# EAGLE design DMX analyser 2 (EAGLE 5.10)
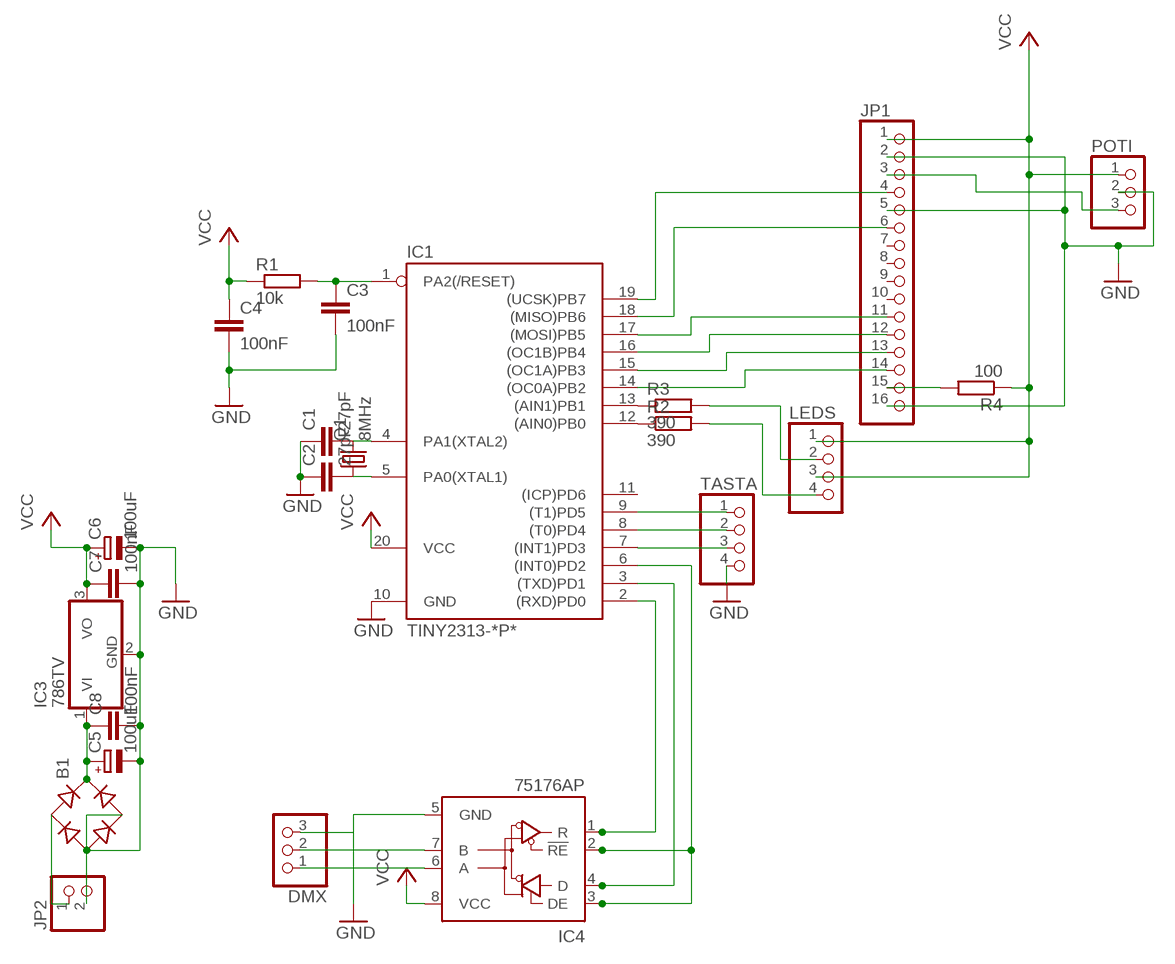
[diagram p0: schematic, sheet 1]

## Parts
B1  RB1A  [RB1A]
C1  27pF  C2,5-3  [C2.5-3]
C2  27pF  C2,5-3  [C2.5-3]
C3  100nF  C-EU025-024X044  [C025-024X044]
C4  100nF  C-EU025-024X044  [C025-024X044]
C5  100uF  CPOL-EUE2.5-6  [E2,5-6]
C6  100uF  CPOL-EUE2.5-6  [E2,5-6]
C7  100nF  C-EU025-024X044  [C025-024X044]
C8  100nF  C-EU025-024X044  [C025-024X044]
DMX  PINHD-1X3/90  [1X03/90]
IC1  TINY2313-*P*  [DIL20]
IC3  786TV  [TO220V]
IC4  75176AP  [DIL08]
JP1  PINHD-1X16  [1X16]
JP2  PINHD-1X2/90  [1X02/90]
LEDS  PINHD-1X4/90  [1X04/90]
POTI  PINHD-1X3/90  [1X03/90]
Q1  8MHz  CRYSTALHC49S  [HC49/S]
R1  10k  R-EU_0204/2V  [0204V]
R2  390  R-EU_0204/2V  [0204V]
R3  390  R-EU_0204/2V  [0204V]
R4  100  R-EU_0204/2V  [0204V]
TASTA  PINHD-1X4/90  [1X04/90]

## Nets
GND: B1.- C1.1 C2.1 C3.2 C4.2 C5.- C6.- C7.2 C8.2 DMX.3 IC1.10(GND) IC3.2(GND) IC4.5(GND) JP1.2 JP1.5 JP1.16 POTI.2 TASTA.4
N$1: C1.2 IC1.4(PA1(XTAL2)) Q1.2
N$2: C2.2 IC1.5(PA0(XTAL1)) Q1.1
N$3: DMX.2 IC4.7(B)
N$4: DMX.1 IC4.6(A)
N$5: IC1.19((UCSK)PB7) JP1.4
N$6: JP1.3 POTI.3
N$7: IC1.2((RXD)PD0) IC4.1(R)
N$8: IC1.3((TXD)PD1) IC4.4(D)
N$9: IC1.7((INT1)PD3) TASTA.3
N$10: IC1.18((MISO)PB6) JP1.6
N$11: IC1.13((AIN1)PB1) R3.1
N$12: IC1.12((AIN0)PB0) R2.1
N$13: IC1.8((T0)PD4) TASTA.2
N$14: IC1.9((T1)PD5) TASTA.1
N$15: B1.AC1 JP2.1
N$16: B1.+ C5.+ C8.1 IC3.1(VI)
N$17: IC1.6((INT0)PD2) IC4.2(!RE) IC4.3(DE)
N$18: IC1.17((MOSI)PB5) JP1.11
N$19: IC1.16((OC1B)PB4) JP1.12
N$20: IC1.15((OC1A)PB3) JP1.13
N$21: IC1.14((OC0A)PB2) JP1.14
N$22: LEDS.2 R3.2
N$23: LEDS.4 R2.2
N$24: C3.1 IC1.1(PA2(/RESET)) R1.2
N$26: JP1.15 R4.2
N$27: B1.AC2 JP2.2
VCC: C4.1 C6.+ C7.1 IC1.20(VCC) IC3.3(VO) IC4.8(VCC) JP1.1 LEDS.1 LEDS.3 POTI.1 R1.1 R4.1
Unconnected: IC1.11((ICP)PD6) JP1.7 JP1.8 JP1.9 JP1.10

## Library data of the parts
B1 = rectifier:RB1A: RECTIFIER 1 A
C1 C2 = capacitor-wima:C: CAPACITOR
C3 C4 C7 C8 = rcl:C-EU: CAPACITOR, European symbol
C5 C6 = rcl:CPOL-EU: POLARIZED CAPACITOR, European symbol
DMX POTI = pinhead:PINHD-1X3: PIN HEADER
IC1 = avr-6:TINY2313*: Atmel Tiny2313 2K Flash, 128 bytes EEPROM, 128 bytes RAM
IC3 = linear:78*: Positive VOLTAGE REGULATOR Source: http://cache.national.com/ds/LM/LM78L05.pdf http://www.fairchildsemi.com/ds/LM/LM7805.pdf
IC4 = 751xx:75176A: DIFFERENTIAL BUS TRANSCEIVER Source: http://focus.ti.com/lit/ds/symlink/sn75176a.pdf
JP1 = pinhead:PINHD-1X16: PIN HEADER
JP2 = pinhead:PINHD-1X2: PIN HEADER
LEDS TASTA = pinhead:PINHD-1X4: PIN HEADER
Q1 = crystal:CRYSTAL: CRYSTAL; OC_FARNELL: 1667008; OC_NEWARK: unknown
R1-R4 = rcl:R-EU_: RESISTOR, European symbol

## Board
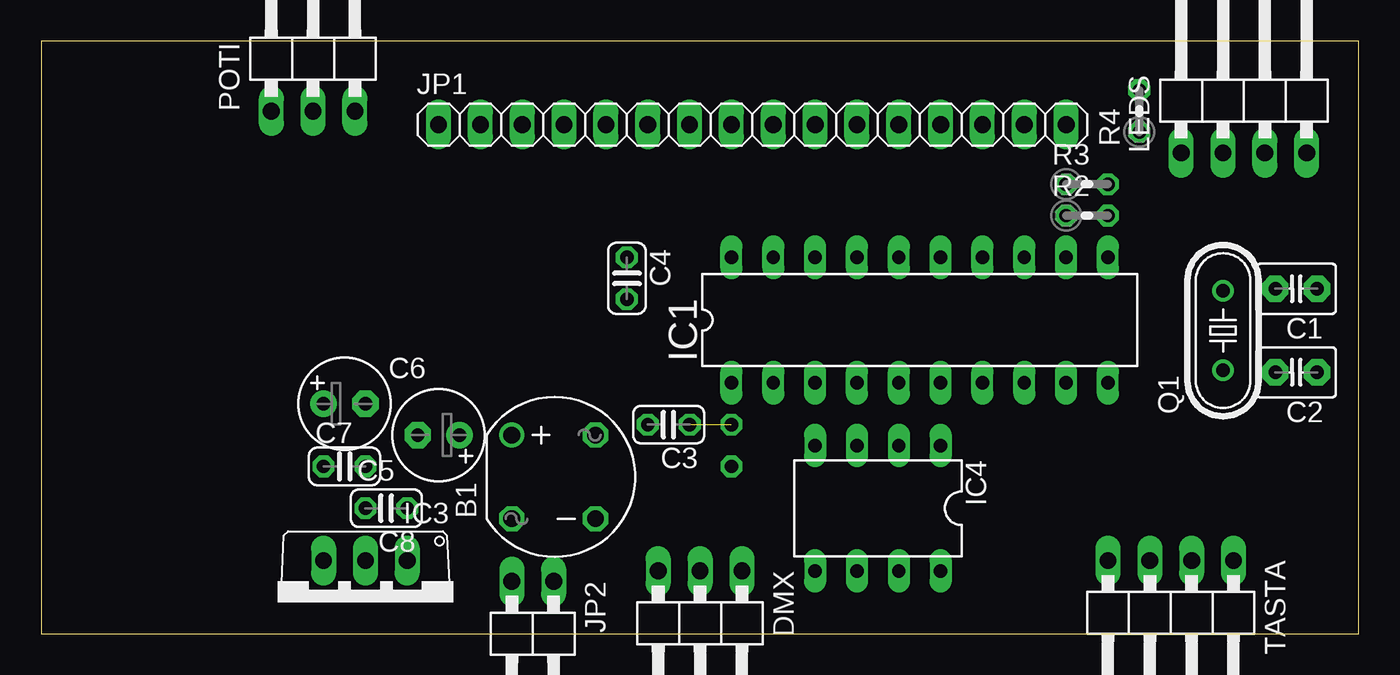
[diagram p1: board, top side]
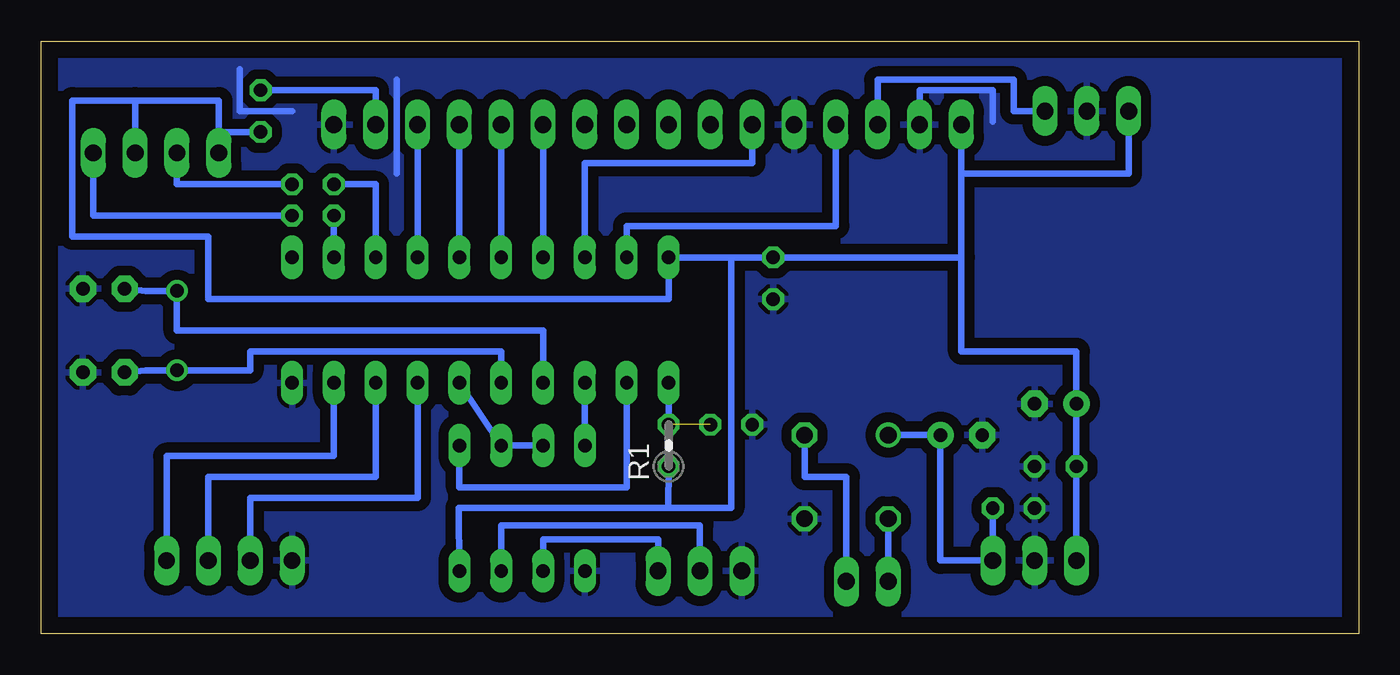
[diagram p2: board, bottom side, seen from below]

Size 80 x 36 mm. Coordinates in mm from the lower left corner, seen from the top.
Outline: 0,0 80,0 80,36 0,36 0,0
Copper layers (1*16): Top 0.035mm / dielectric 1.5mm / Bottom 0.035mm
Design rules "default": minimum track width 10mil, minimum drill 24mil, track to track 8mil, track to pad 8mil, pad to pad 8mil, via to via 8mil, smd to smd 8mil, copper to edge 40mil, drill to drill 8mil, minimum pad ring 10mil, minimum via ring 8mil, stop-mask expansion 4mil, vias tented up to drill 0mil, thermal gap 10mil

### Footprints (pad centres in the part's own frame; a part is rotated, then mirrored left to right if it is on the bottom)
RB1A = drill 1.016 round: + -2.54,2.54 | drill 1.016 octagon: - 2.54,-2.54; AC1 2.54,2.54; AC2 -2.54,-2.54
C2.5-3 = drill 0.813 pad 1.6 octagon: 1 -1.27,0; 2 1.27,0
C025-024X044 = drill 0.813 octagon: 1 -1.27,0; 2 1.27,0
E2,5-6 = drill 0.813 pad 1.6 round: + -1.27,0 | drill 0.813 pad 1.6 octagon: - 1.27,0
1X03/90 = drill 1.016 long: 1 -2.54,-3.81; 2 0,-3.81; 3 2.54,-3.81
DIL20 = drill 0.813 long: 1 -11.43,-3.81; 2 -8.89,-3.81; 3 -6.35,-3.81; 4 -3.81,-3.81; 5 -1.27,-3.81; 6 1.27,-3.81; 7 3.81,-3.81; 8 6.35,-3.81; 9 8.89,-3.81; 10 11.43,-3.81; 11 11.43,3.81; 12 8.89,3.81; 13 6.35,3.81; 14 3.81,3.81; 15 1.27,3.81; 16 -1.27,3.81; 17 -3.81,3.81; 18 -6.35,3.81; 19 -8.89,3.81; 20 -11.43,3.81
TO220V = drill 1.016 long: 1 -2.54,-2.54; 2 0,-2.54; 3 2.54,-2.54
DIL08 = drill 0.813 long: 1 -3.81,-3.81; 2 -1.27,-3.81; 3 1.27,-3.81; 4 3.81,-3.81; 5 3.81,3.81; 6 1.27,3.81; 7 -1.27,3.81; 8 -3.81,3.81
1X16 = drill 1.016 long: 1 -19.05,0; 2 -16.51,0; 3 -13.97,0; 4 -11.43,0; 5 -8.89,0; 6 -6.35,0; 7 -3.81,0; 8 -1.27,0; 9 1.27,0; 10 3.81,0; 11 6.35,0; 12 8.89,0; 13 11.43,0; 14 13.97,0; 15 16.51,0; 16 19.05,0
1X02/90 = drill 1.016 long: 1 -1.27,-3.81; 2 1.27,-3.81
1X04/90 = drill 1.016 long: 1 -3.81,-3.81; 2 -1.27,-3.81; 3 1.27,-3.81; 4 3.81,-3.81
HC49/S = drill 0.813 round: 1 -2.413,0; 2 2.413,0
0204V = drill 0.813 octagon: 1 -1.27,0; 2 1.27,0

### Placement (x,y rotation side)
B1  31.11,9.53 0 top
C1  76.2,20.95 180 top
C2  76.2,15.88 180 top
C3  38.1,12.7 180 top
C4  35.56,21.59 270 top
C5  24.13,12.06 180 top
C6  18.41,13.97 0 top
C7  18.41,10.16 0 top
C8  20.95,7.62 180 top
DMX  40.01,0 180 top
IC1  53.34,19.05 0 top
IC3  19.68,1.91 180 top
IC4  50.8,7.62 180 top
JP1  43.18,30.93 0 top
JP2  29.84,-0.64 180 top
LEDS  73.03,33.02 0 top
POTI  16.51,35.56 0 top
Q1  71.75,18.41 90 top
R1  41.91,11.43 90 bottom
R2  63.5,25.4 0 top
R3  63.5,27.3 0 top
R4  66.67,31.75 90 top
TASTA  68.58,0.64 180 top

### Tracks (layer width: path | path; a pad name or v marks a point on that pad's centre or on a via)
GND
  Bottom 0.406: JP1.2 26.67,33.02 22.23,33.02 22.23,31.11 | 64.77,31.75 67.94,31.75 67.94,34.29 | 58.42,27.94 58.42,33.66
  pour Bottom (isolate 0.61): 0,36.2 80.01,36.2 80.01,0 0,0
N$1
  Bottom 0.406: IC1.4 49.53,18.41 71.75,18.41 Q1.2 73.66,20.83 C1.2
N$2
  Bottom 0.406: IC1.5 52.07,17.14 67.31,17.14 67.31,16 Q1.1 73.66,16 C2.2
N$3
  Bottom 0.406: IC4.7 52.07,6.59 40.01,6.59 DMX.2
N$4
  Bottom 0.406: DMX.1 42.55,5.71 49.53,5.71 IC4.6
N$5
  Bottom 0.406: IC1.19 44.45,24.77 31.75,24.77 31.75,31.57 JP1.4
N$6
  Bottom 0.406: JP1.3 29.21,33.66 20.95,33.66 20.95,31.75 POTI.3
N$7
  Bottom 0.406: IC1.2 44.45,8.89 54.61,8.89 IC4.1
N$8
  Bottom 0.406: IC4.4 IC1.3
N$9
  Bottom 0.406: IC1.7 57.15,8.26 67.31,8.26 TASTA.3
N$10
  Bottom 0.406: IC1.18 46.99,28.57 36.83,28.57 36.83,31.57 JP1.6
N$11
  Bottom 0.406: R3.1 59.69,27.3 IC1.13
N$12
  Bottom 0.406: IC1.12 R2.1
N$13
  Bottom 0.406: IC1.8 59.69,9.53 69.85,9.53 TASTA.2
N$14
  Bottom 0.406: IC1.9 62.23,10.79 72.39,10.79 TASTA.1
N$15
  Bottom 0.406: B1.AC1 33.66,9.53 31.11,9.53 JP2.1
N$16
  Bottom 0.406: B1.+ C5.+ 25.4,4.45 IC3.1 C8.1
N$17
  Bottom 0.406: IC1.6 IC4.2 IC4.3
N$18
  Bottom 0.406: IC1.17 JP1.11 | IC1.17
N$19
  Bottom 0.406: IC1.16 52.07,31.57 JP1.12
N$20
  Bottom 0.406: IC1.15 JP1.13 | IC1.15
N$21
  Bottom 0.406: IC1.14 57.15,31.57 JP1.14
N$22
  Bottom 0.406: R3.2 71.75,27.3 LEDS.2
N$23
  Bottom 0.406: R2.2 76.83,25.4 LEDS.4
N$24  (1 unrouted)
  Bottom 0.406: R1.2 IC1.1
N$26
  Bottom 0.406: 59.69,30.3 JP1.15 59.69,33.02 R4.2
N$27
  Bottom 0.406: JP2.2 B1.AC2
VCC
  Bottom 0.406: 24.13,22.86 24.13,27.94 | 24.13,27.94 24.13,30.3 JP1.1 | IC4.8 54.64,7.65 41.94,7.65 | 41.94,7.65 38.1,7.65 38.1,22.86 | 38.1,22.86 IC1.20 41.91,20.32 69.85,20.32 69.85,24.13 78.11,24.13 78.11,32.38 74.3,32.38 | 74.3,32.38 LEDS.3 | 69.22,30.48 69.22,32.38 74.3,32.38 | 69.22,30.48 LEDS.1 | 69.22,30.48 R4.1 | 41.94,7.65 R1.1 | 38.1,22.86 C4.1 24.13,22.86 | IC3.3 C7.1 C6.+ 17.14,17.14 24.13,17.14 24.13,22.86 | POTI.1 13.97,27.94 24.13,27.94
